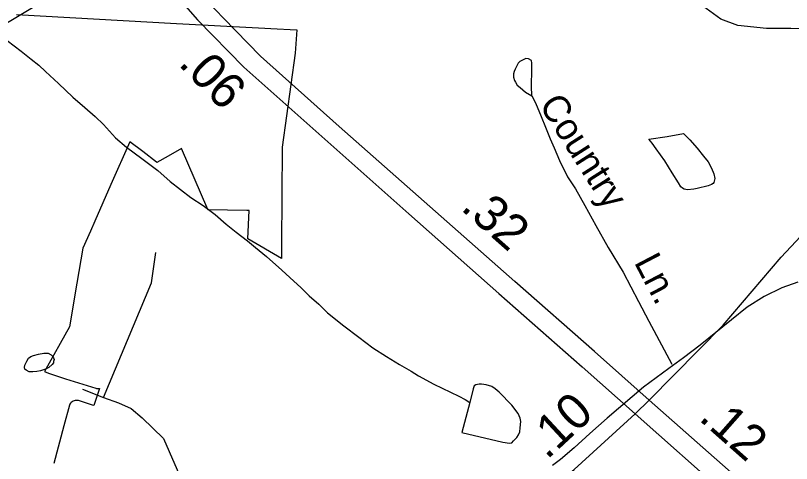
# Model space of a CAD drawing. Extents: x 2001466 to 2224147, y 644118 to 847247.
# Drawn here: x 2045643 to 2048372, y 688676 to 690251 of the extents above; entities that cross this region are included whole.
import ezdxf

# ---------------------------------------------------------------- set-up
doc = ezdxf.new("R2010")
doc.units = 0
for name, color, linetype in [('Exist Boundary Political City Limit New', 7, 'Continuous'), ('Exist Hydrographic Creek Single Shore', 7, 'Continuous'), ('Exist Hydrographic Misc Water Feature', 7, 'Continuous'), ('Exist Road Non-System Type 51', 7, 'Continuous'), ('Exist Road Non-System Type 51 Label', 7, 'Continuous'), ('Exist Road Primary NC Divided Attributed', 7, 'Continuous'), ('Exist Road Primary NC Service Mileage Hundredths English Label', 7, 'Continuous'), ('Exist Road Secondary Mileage Hundredths English Label', 7, 'Continuous'), ('Exist Road Secondary Type 51 Attributed', 7, 'Continuous'), ('Map Preparation Boundary City Limit Buffer Line', 7, 'Continuous')]:
    doc.layers.add(name, color=color, linetype=linetype)

msp = doc.modelspace()

# ---------------------------------------------------------------- linework, layer by layer
at = {"layer": 'Exist Boundary Political City Limit New'}
for points in [[(2045646.4, 690254.7), (2046209.5, 690223.7), (2046497.6, 690207.9), (2046563.2, 690204.2), (2046608.9, 690201.8), (2046633.2, 690200.4), (2046627.2, 690118.9), (2046581, 689788.6), (2046579.1, 689446.6), (2046578.9, 689397.1), (2046459.8, 689466.4), (2046465.4, 689566.2), (2046456.6, 689566.4), (2046320.9, 689567.9), (2046320.1, 689569.6), (2046226.6, 689783.5), (2046179.5, 689756.6), (2046140.6, 689734.4), (2046138.9, 689735.8), (2046091, 689772.7), (2046045.5, 689807.8), (2045978.9, 689656.9), (2045922.1, 689528.4), (2045906.5, 689493.1), (2045880.2, 689433.6), (2045859, 689310.3), (2045832.5, 689156.5), (2045744.8, 688999.9), (2045758.8, 688994.4), (2045772.9, 688989.3), (2045787.1, 688984.6), (2045819.4, 688974.4), (2045925.1, 688941.1), (2045928.4, 688940.2), (2045929.5, 688940.1), (2045931.8, 688939.9), (2045935.1, 688940), (2045938.4, 688940.5), (2045919.2, 688880), (2045913.5, 688881.8), (2045864.4, 688897.3), (2045860.6, 688898.2), (2045856.6, 688898.4), (2045852.8, 688898.1)], [(2045852.8, 688898.1), (2045849, 688897.2), (2045846.2, 688896.1), (2045845.4, 688895.6), (2045842.6, 688893.9), (2045842, 688893.6), (2045839.1, 688891), (2045836.5, 688888), (2045834.5, 688884.6), (2045833, 688881), (2045813.5, 688809.1), (2045777.4, 688675.9)]]:
    msp.add_lwpolyline(points, dxfattribs=at)
at = {"layer": 'Exist Hydrographic Creek Single Shore'}
msp.add_lwpolyline([(2042866.1, 689196.4), (2042905, 689208.6), (2043363.1, 689448.6), (2044504, 689760.1), (2045328.1, 690055.1), (2045714.7, 690286.8)], dxfattribs=at)
at = {"layer": 'Exist Hydrographic Misc Water Feature'}
for points in [[(2045614.3, 690163.9), (2045662.5, 690126.1), (2045698.6, 690098.1), (2045724.7, 690076.2), (2045748.7, 690054.2), (2045794.6, 690012.3), (2045844.8, 689964.4), (2045886.9, 689928.5), (2045923, 689896.6), (2045952.9, 689868.6), (2045995.1, 689820.7), (2046033.1, 689788.8), (2046087.2, 689748.9), (2046143.2, 689707), (2046187.3, 689667.2), (2046223.4, 689639.2), (2046259.4, 689611.3), (2046303.3, 689583.4), (2046345.4, 689551.5), (2046383.5, 689517.5), (2046419.6, 689489.6), (2046459.6, 689459.7), (2046487.7, 689435.7), (2046525.6, 689403.8), (2046579.7, 689355.9), (2046607.8, 689329.9), (2046647.8, 689294.1), (2046675.9, 689266.1), (2046709.9, 689236.2), (2046740.1, 689206.2), (2046798.1, 689160.4), (2046850.2, 689120.4), (2046900.2, 689082.6), (2046948.2, 689052.7), (2046994.3, 689024.8), (2047034.3, 689000.8), (2047060.4, 688984.9), (2047114.3, 688955), (2047202.5, 688913.1), (2047224.6, 688901.2), (2047240.6, 688891.3)], [(2047934.7, 689826.4), (2047992.7, 689836.5), (2048014.7, 689814.5), (2048040.7, 689784.6), (2048062.9, 689756.7), (2048078.9, 689736.7), (2048090.8, 689714.7), (2048099, 689694.7), (2048102.9, 689678.7), (2048099, 689664.7), (2048096.9, 689660.7), (2048091, 689656.7), (2048078.9, 689652.7), (2048040.9, 689642.6), (2048029, 689640.6), (2048007.1, 689638.6), (2047995, 689640.5), (2047989.1, 689644.5), (2047983.1, 689648.5), (2047974.9, 689662.5), (2047953, 689698.5), (2047926.7, 689740.4), (2047896.8, 689782.3), (2047882.6, 689802.3), (2047870.7, 689816.3), (2047934.7, 689826.4)], [(2048394.2, 689314.4), (2048338.3, 689294.5), (2048275.9, 689264)], [(2048394.2, 689314.4), (2048338.3, 689294.5), (2048275.9, 689264)], [(2048275.9, 689264), (2048217.1, 689226.3), (2048050.8, 689092.7), (2047993, 689048.3), (2047941.3, 689010.2)], [(2048275.9, 689264), (2048217.1, 689226.3), (2048050.8, 689092.7), (2047993, 689048.3), (2047941.3, 689010.2)], [(2045742.5, 689064.4), (2045754.4, 689064.4), (2045758.5, 689064.5), (2045768.5, 689058.5), (2045772.4, 689054.5), (2045776.5, 689048.4), (2045778.6, 689042.4), (2045776.5, 689034.4), (2045776.5, 689030.4), (2045772.4, 689024.4), (2045760.5, 689014.4), (2045748.5, 689008.4), (2045730.6, 689002.4), (2045718.5, 689000.4), (2045704.6, 688998.3), (2045694.7, 688998.3), (2045690.6, 688998.3), (2045680.6, 689004.2), (2045676.5, 689008.3), (2045674.6, 689014.3), (2045676.5, 689022.3), (2045682.6, 689036.3), (2045688.6, 689046.3), (2045696.6, 689052.3), (2045706.6, 689056.3), (2045724.5, 689060.4), (2045742.5, 689064.4)], [(2047941.3, 689010.2), (2047852.3, 688944.3), (2047723.9, 688835.8), (2047663.6, 688781.3)], [(2047941.3, 689010.2), (2047852.3, 688944.3), (2047723.9, 688835.8), (2047663.6, 688781.3)], [(2047240.6, 688891.3), (2047212.7, 688785.2), (2047356.7, 688751.5), (2047380.7, 688747.5), (2047388.7, 688749.6), (2047394.8, 688755.6), (2047406.7, 688767.6), (2047412.7, 688777.6), (2047416.5, 688787.6), (2047418.6, 688801.6), (2047420.7, 688823.6), (2047418.6, 688835.6), (2047410.6, 688851.6), (2047388.5, 688881.5), (2047344.4, 688927.5), (2047330.4, 688939.4), (2047318.3, 688947.4), (2047298.4, 688953.3), (2047282.4, 688955.3), (2047274.4, 688955.3), (2047262.4, 688953.3), (2047256.4, 688949.3), (2047252.3, 688939.3), (2047240.6, 688891.3)], [(2047663.6, 688781.3), (2047608.1, 688731.3), (2047559.9, 688690.1), (2047531.8, 688669.7)], [(2047663.6, 688781.3), (2047608.1, 688731.3), (2047559.9, 688690.1), (2047531.8, 688669.7)]]:
    msp.add_lwpolyline(points, dxfattribs=at)
at = {"layer": 'Exist Road Non-System Type 51'}
msp.add_line((2045878.5, 688937.6), (2045952.4, 688909), dxfattribs=at)
for points in [[(2048717.2, 690224.4), (2048533.2, 690202.6), (2048370.2, 690206.1), (2048284.1, 690206.1), (2048184.2, 690215.7), (2048123.9, 690238.7), (2048046.7, 690295.1), (2047871.3, 690433.1), (2047817.7, 690505.5), (2047779.6, 690598)], [(2047459, 689969.2), (2047457.7, 690003.2), (2047458.9, 690061.2), (2047459.3, 690083.2), (2047457.5, 690093.2), (2047447.6, 690099.4), (2047437.6, 690099.6), (2047417.4, 690090), (2047411.3, 690084.2), (2047407.2, 690076.3), (2047400.9, 690062.4), (2047396.7, 690054.5), (2047394.6, 690046.5), (2047394.3, 690034.5), (2047398.1, 690022.4), (2047401.9, 690016.4), (2047407.7, 690006.2), (2047417.6, 689998), (2047437.2, 689981.6), (2047459, 689969.2)], [(2047459, 689969.2), (2047472.5, 689944.9), (2047491.5, 689896.5), (2047506.7, 689858.2), (2047523.9, 689817.9), (2047537.2, 689785.6), (2047556.3, 689741.2), (2047585.2, 689684.6), (2047612.3, 689642.1), (2047645.1, 689583.4), (2047683.7, 689512.6), (2047728.1, 689435.7), (2047780.3, 689348.6), (2047834.2, 689245.5), (2047870.8, 689176.8), (2047951.7, 689025.1)], [(2045952.4, 688909), (2046121.9, 689311.3), (2046136.5, 689418)], [(2045952.4, 688909), (2046005.7, 688889.6), (2046050.4, 688870.2), (2046089, 688837.5), (2046164.2, 688764.1), (2046203.7, 688673.4), (2046233.9, 688603.6), (2046266.4, 688552.5), (2046329.2, 688496.7), (2046448.1, 688436.7), (2046522.3, 688395.1), (2046654.6, 688303.6), (2046753.8, 688193.2), (2046856.3, 688104.2)]]:
    msp.add_lwpolyline(points, dxfattribs=at)
at = {"layer": 'Exist Road Primary NC Divided Attributed'}
for points in [[(2044951.7, 694316.9), (2044943.8, 694099.8), (2044964.9, 693752.8), (2044987.8, 693599.7), (2045024.4, 693410.1), (2045083, 693142.4), (2045209, 692616.6), (2045351.9, 691992.6), (2045392.5, 691826.9), (2045455.3, 691627.8), (2045564.2, 691342), (2045637.5, 691182.4), (2045694.2, 691071.8), (2045787.6, 690902.7), (2045894.3, 690733.7), (2046022.2, 690554.6), (2046110, 690435.6), (2046200, 690332.2), (2046283.4, 690236.5), (2046445.7, 690069.7), (2047026.3, 689553.6), (2047343.5, 689274), (2047635.7, 689015.7), (2047822.5, 688851.2)], [(2047871.5, 688899.5), (2047679.1, 689070.2), (2047399.6, 689316.2), (2047080.7, 689597.7), (2046781.4, 689861.7), (2046504.6, 690108.6), (2046373.4, 690243.2), (2046275.6, 690347.8), (2046172.2, 690469), (2046075.9, 690593.3), (2045958.8, 690758.1), (2045832.1, 690959.4), (2045725.4, 691157.4), (2045669.7, 691280.3), (2045626.4, 691375.4), (2045503.6, 691689), (2045451, 691877), (2045415.6, 692015.7), (2045362.4, 692254), (2045280.2, 692611), (2045118.9, 693291), (2045077.9, 693488.5)], [(2049542, 687710.8), (2049366.1, 687806.8), (2049025.8, 687972.4), (2048863.2, 688061.5), (2048737, 688147.2), (2048603.6, 688254.3), (2048403.1, 688430.9), (2048189.6, 688618.5), (2047871.5, 688899.5)], [(2047822.5, 688851.2), (2048145.6, 688564.7), (2048554.4, 688206.3), (2048660.6, 688119.4), (2048741.7, 688060.4), (2048806.5, 688018.7), (2048893.3, 687966.6), (2049039.7, 687889), (2049349.9, 687738.4), (2049506.4, 687658.6)]]:
    msp.add_lwpolyline(points, dxfattribs=at)
at = {"layer": 'Exist Road Secondary Type 51 Attributed'}
for points in [[(2047871.5, 688899.5), (2048132.3, 689162.2), (2048336, 689402), (2048594.1, 689676.6), (2048716.6, 689821.3), (2048846.9, 690050.5), (2048909.2, 690184.7), (2049015.3, 690487.9), (2049063.9, 690652.6), (2049100.3, 690793.1), (2049123.5, 691082.6), (2049153.1, 691497.7), (2049155.7, 691779.7), (2049158.9, 691902.3), (2049157.3, 691944.9), (2049165.2, 691962.2), (2049175.4, 691972.4), (2049193.5, 691980.3), (2049195.7, 691980.9)], [(2047822.5, 688851.2), (2047871.5, 688899.5)], [(2046639.2, 687708.7), (2046859.3, 687955.8), (2047096.8, 688211.5), (2047394.4, 688481.9), (2047607.7, 688655.1), (2047822.5, 688851.2)]]:
    msp.add_lwpolyline(points, dxfattribs=at)
at = {"layer": 'Map Preparation Boundary City Limit Buffer Line'}
for points in [[(2045646.4, 690254.7), (2046209.5, 690223.7), (2046497.6, 690207.9), (2046563.2, 690204.2), (2046608.9, 690201.8), (2046633.2, 690200.4), (2046627.2, 690118.9), (2046581, 689788.6), (2046579.1, 689446.6), (2046578.9, 689397.1), (2046459.8, 689466.4), (2046465.4, 689566.2), (2046456.6, 689566.4), (2046320.9, 689567.9), (2046320.1, 689569.6), (2046226.6, 689783.5), (2046179.5, 689756.6), (2046140.6, 689734.4), (2046138.9, 689735.8), (2046091, 689772.7), (2046045.5, 689807.8), (2045978.9, 689656.9), (2045922.1, 689528.4), (2045906.5, 689493.1), (2045880.2, 689433.6), (2045859, 689310.3), (2045832.5, 689156.5), (2045744.8, 688999.9), (2045758.8, 688994.4), (2045772.9, 688989.3), (2045787.1, 688984.6), (2045819.4, 688974.4), (2045925.1, 688941.1), (2045928.4, 688940.2), (2045929.5, 688940.1), (2045931.8, 688939.9), (2045935.1, 688940), (2045938.4, 688940.5), (2045919.2, 688880), (2045913.5, 688881.8), (2045864.4, 688897.3), (2045860.6, 688898.2), (2045856.6, 688898.4), (2045852.8, 688898.1)], [(2045852.8, 688898.1), (2045849, 688897.2), (2045846.2, 688896.1), (2045845.4, 688895.6), (2045842.6, 688893.9), (2045842, 688893.6), (2045839.1, 688891), (2045836.5, 688888), (2045834.5, 688884.6), (2045833, 688881), (2045813.5, 688809.1), (2045777.4, 688675.9)]]:
    msp.add_lwpolyline(points, dxfattribs=at)

# ---------------------------------------------------------------- texts
at = {"layer": 'Exist Road Non-System Type 51 Label'}
for s, rotation, p in [('Country', 302.5226, (2047482.2, 689937.7)), ('Ln.', 297.5977, (2047817.3, 689384.1))]:
    msp.add_text(s, height=95, rotation=rotation, dxfattribs=at).set_placement(p)
at = {"layer": 'Exist Road Primary NC Service Mileage Hundredths English Label'}
for s, rotation, p in [('.06', 314.266, (2046212.9, 690078.7)), ('.32', 318.572, (2047205.6, 689570.8)), ('.12', 318.5389, (2048042.8, 688831.6))]:
    msp.add_text(s, height=125, rotation=rotation, dxfattribs=at).set_placement(p)
at = {"layer": 'Exist Road Secondary Mileage Hundredths English Label'}
msp.add_text('.10', height=125, rotation=42.8858, dxfattribs=at).set_placement((2047512.3, 688687.5))

doc.saveas('drawing.dxf')
